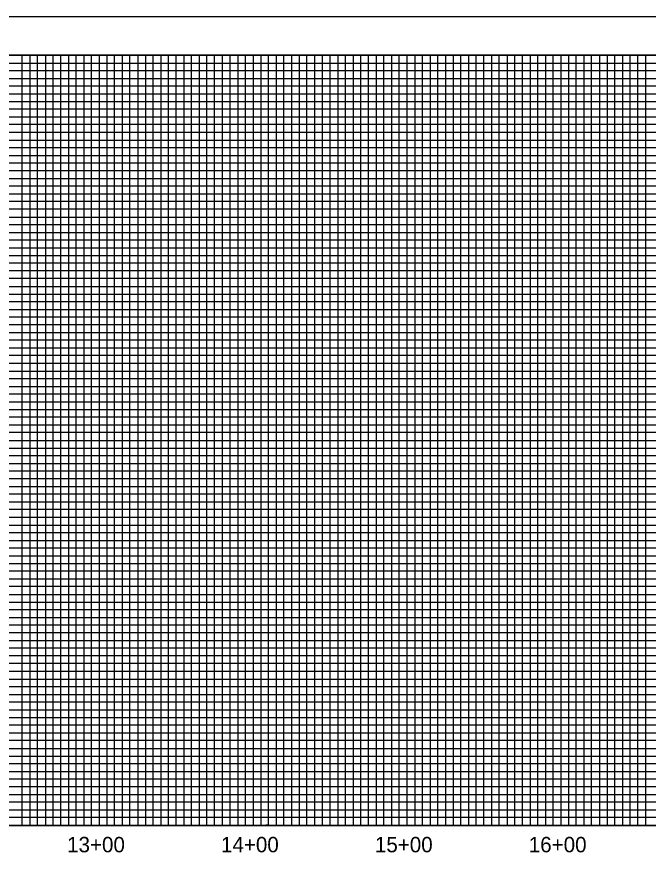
# Model space of a CAD drawing. Extents: x 505602 to 507286, y 483109 to 489436.
# Drawn here: x 506466 to 506876, y 483662 to 484209 of the extents above; entities that cross this region are included whole.
import ezdxf

# ---------------------------------------------------------------- set-up
doc = ezdxf.new("R2010")
doc.units = 0
for name, color, linetype in [('Exist Vertical Profile Vertical Axis Label', 7, 'Continuous'), ('Sheet Layout Profile Border Port 1', 7, 'Continuous'), ('Sheet Plot Border Outside CELL', 7, 'Continuous'), ('Sheet Profile CELL', 7, 'Continuous'), ('Sheet Profile Grid Major CELL', 7, 'Continuous'), ('Sheet Profile Grid Middle CELL', 7, 'Continuous'), ('Sheet Profile Grid Minor CELL', 7, 'Continuous')]:
    doc.layers.add(name, color=color, linetype=linetype)

msp = doc.modelspace()

# ---------------------------------------------------------------- linework, layer by layer
at = {"layer": 'Sheet Layout Profile Border Port 1'}
msp.add_lwpolyline([(506119.08, 484183.71), (507069.08, 484183.71), (507069.08, 483683.71), (506119.08, 483683.71)], close=True, dxfattribs=at)
at = {"layer": 'Sheet Plot Border Outside CELL'}
msp.add_lwpolyline([(505602.08, 483108.71), (507286.08, 483108.71), (507286.08, 484208.71), (505602.08, 484208.71)], close=True, dxfattribs=at)
at = {"layer": 'Sheet Profile CELL'}
msp.add_line((505769.08, 483683.71), (507269.08, 483683.71), dxfattribs=at)
msp.add_lwpolyline([(507269.08, 484183.71), (505769.08, 484183.71), (505769.08, 483133.71), (507269.08, 483133.71)], close=True, dxfattribs=at)
at = {"layer": 'Sheet Profile Grid Major CELL'}
for points in [[(506419.08, 483683.71), (506469.08, 483683.71), (506469.08, 484183.71), (506519.08, 484183.71), (506519.08, 483683.71), (506569.08, 483683.71), (506569.08, 484183.71), (506619.08, 484183.71), (506619.08, 483683.71), (506669.08, 483683.71), (506669.08, 484183.71), (506719.08, 484183.71), (506719.08, 483683.71), (506769.08, 483683.71), (506769.08, 484183.71), (506819.08, 484183.71), (506819.08, 483683.71), (506869.08, 483683.71), (506869.08, 484183.71), (506919.08, 484183.71)], [(505769.08, 484133.71), (507069.08, 484133.71)], [(507069.08, 484083.71), (505769.08, 484083.71), (505769.08, 484033.71), (507069.08, 484033.71)], [(507269.08, 483983.71), (505769.08, 483983.71), (505769.08, 483933.71), (507269.08, 483933.71)], [(507269.08, 483883.71), (505769.08, 483883.71), (505769.08, 483833.71), (507269.08, 483833.71)], [(507269.08, 483783.71), (505769.08, 483783.71), (505769.08, 483783.71), (505769.08, 483733.71), (507269.08, 483733.71)]]:
    msp.add_lwpolyline(points, dxfattribs=at)
at = {"layer": 'Sheet Profile Grid Middle CELL'}
msp.add_line((505769.08, 484158.71), (507069.03, 484158.71), dxfattribs=at)
msp.add_line((505769.08, 484158.71), (507069.03, 484158.71), dxfattribs=at)
for points in [[(506444.08, 483683.71), (506494.08, 483683.71), (506494.08, 484183.71), (506544.08, 484183.71), (506544.08, 483683.71), (506594.08, 483683.71), (506594.08, 484183.71), (506644.08, 484183.71), (506644.08, 483683.71), (506694.08, 483683.71), (506694.08, 484183.71), (506744.08, 484183.71), (506744.08, 483683.71), (506794.08, 483683.71), (506794.08, 484183.71), (506844.08, 484183.71), (506844.08, 483683.71), (506894.08, 483683.71)], [(507069.08, 484108.71), (505769.08, 484108.71), (505769.08, 484058.71), (507069.08, 484058.71)], [(507269.08, 484008.71), (505769.08, 484008.71), (505769.08, 483958.71), (507094.08, 483958.71)], [(507269.08, 483908.71), (505769.08, 483908.71), (505769.08, 483858.71), (507269.08, 483858.71)], [(507269.08, 483808.71), (505769.08, 483808.71), (505769.08, 483758.71), (507269.08, 483758.71)], [(507269.08, 483708.71), (505769.08, 483708.71)]]:
    msp.add_lwpolyline(points, dxfattribs=at)
at = {"layer": 'Sheet Profile Grid Minor CELL'}
for p, q in [((505819.08, 484178.71), (507069.08, 484178.71)), ((507069.08, 484173.71), (505819.08, 484173.36)), ((505819.08, 484168.71), (507069.08, 484168.71)), ((507069.03, 484048.71), (505819.08, 484048.71)), ((507069.08, 484043.71), (505819.08, 484043.71)), ((507069.08, 484038.71), (505819.08, 484038.71)), ((505819.08, 484028.71), (507069.08, 484028.71)), ((507069.08, 484023.71), (505819.08, 484023.71)), ((505819.08, 484018.71), (507219.08, 484018.71)), ((507219.08, 483998.71), (505819.08, 483998.71)), ((505819.08, 483993.71), (507219.08, 483993.71)), ((507219.08, 483973.71), (505819.08, 483973.71)), ((505819.08, 483968.71), (507219.08, 483968.71)), ((507219.08, 483948.71), (505819.08, 483948.71)), ((505819.08, 483943.71), (507219.08, 483943.71)), ((507219.08, 483938.71), (505819.08, 483938.71)), ((505819.08, 483928.71), (507219.08, 483928.71)), ((507219.08, 483923.71), (505819.08, 483923.71)), ((505819.08, 483918.71), (507219.08, 483918.71)), ((507219.08, 483913.71), (505819.08, 483913.71)), ((505819.08, 483903.71), (507219.08, 483903.71)), ((507219.08, 483898.71), (505819.08, 483898.71)), ((505819.08, 483893.71), (507219.08, 483893.71)), ((507219.08, 483888.71), (505819.08, 483888.71)), ((505819.08, 483878.71), (507219.08, 483878.71)), ((507219.08, 483873.71), (505819.08, 483873.71)), ((505819.08, 483868.71), (507219.08, 483868.71)), ((507219.08, 483863.71), (505819.08, 483863.71)), ((505819.08, 483853.71), (507219.08, 483853.71)), ((507219.08, 483848.71), (505819.08, 483848.71)), ((505819.08, 483843.71), (507219.08, 483843.71)), ((507219.08, 483838.71), (505819.08, 483838.71)), ((505819.08, 483828.71), (507219.08, 483828.71)), ((507219.08, 483823.71), (505819.08, 483823.71)), ((505819.08, 483818.71), (507219.08, 483818.71)), ((507219.08, 483813.71), (505819.08, 483813.71)), ((505819.08, 483803.71), (507219.08, 483803.71)), ((507219.08, 483798.71), (505819.08, 483798.71)), ((507219.08, 483793.71), (505819.08, 483793.71)), ((507219.08, 483788.71), (505819.08, 483788.71)), ((505819.08, 483778.71), (507219.08, 483778.71)), ((507219.08, 483773.71), (505819.08, 483773.71)), ((505819.08, 483768.71), (507219.08, 483768.71)), ((507219.08, 483763.71), (505819.08, 483763.71)), ((505819.08, 483753.71), (507219.08, 483753.71)), ((507219.08, 483748.71), (505819.08, 483748.71)), ((505819.08, 483743.71), (507219.08, 483743.71)), ((507219.08, 483738.71), (505819.08, 483738.71)), ((505819.08, 483728.71), (507219.08, 483728.71)), ((507219.08, 483723.71), (505819.08, 483723.71)), ((505819.08, 483718.71), (507219.08, 483718.71)), ((507219.08, 483713.71), (505819.08, 483713.71)), ((505819.08, 483703.71), (507219.08, 483703.71)), ((507219.08, 483698.71), (505819.08, 483698.71)), ((505819.08, 483693.71), (507219.08, 483693.71))]:
    msp.add_line(p, q, dxfattribs=at)
for points in [[(506464.08, 484183.71), (506474.08, 484183.71), (506474.08, 483683.71), (506474.08, 483683.71), (506479.08, 483683.71), (506479.08, 484183.71), (506484.08, 484183.71), (506484.08, 483683.71), (506489.08, 483683.71), (506489.08, 484183.71), (506499.08, 484183.71), (506499.08, 483683.71), (506504.08, 483683.71), (506504.08, 484183.71), (506509.08, 484183.71), (506509.08, 483683.71), (506514.08, 483683.71), (506514.08, 484183.71), (506524.08, 484183.71), (506524.08, 483683.71), (506529.08, 483683.71), (506529.08, 484183.71), (506534.08, 484183.71), (506534.08, 483683.71), (506539.08, 483683.71), (506539.08, 484183.71), (506549.08, 484183.71), (506549.08, 483683.71), (506554.08, 483683.71), (506554.08, 484183.71), (506559.08, 484183.71), (506559.08, 483683.71), (506564.08, 483683.71), (506564.08, 484183.71), (506574.08, 484183.71), (506574.08, 483683.71), (506579.08, 483683.71), (506579.08, 484183.71), (506584.08, 484183.71), (506584.08, 483683.71), (506589.08, 483683.71), (506589.08, 484183.71), (506599.08, 484183.71), (506599.08, 483683.71), (506604.08, 483683.71), (506604.08, 484183.71), (506609.08, 484183.71), (506609.08, 483683.71), (506614.08, 483683.71), (506614.08, 484183.71), (506624.08, 484183.71), (506624.08, 483683.71), (506628.78, 483684.26), (506629.08, 483683.71), (506629.08, 484183.71), (506634.08, 484183.71), (506634.08, 483683.71), (506639.08, 483683.71), (506639.08, 484183.71), (506649.08, 484183.71), (506649.08, 483683.71), (506654.08, 483683.71)], [(506654.08, 483683.71), (506654.08, 484183.71), (506659.08, 484183.71), (506659.08, 483683.71), (506664.08, 483683.71), (506664.08, 484183.71), (506674.08, 484183.71), (506674.08, 483683.71), (506679.08, 483683.71), (506679.08, 484183.71), (506684.08, 484183.71), (506684.08, 483683.71), (506689.08, 483683.71), (506689.08, 484183.71), (506699.08, 484183.71), (506699.08, 483683.71), (506704.08, 483683.71), (506704.08, 484183.71), (506709.08, 484183.71), (506709.08, 483683.71), (506714.08, 483683.71), (506714.08, 484183.71), (506724.08, 484183.71), (506724.08, 483683.71), (506729.08, 483683.71), (506729.08, 484183.71), (506734.08, 484183.71), (506734.08, 483683.71), (506739.08, 483683.71), (506739.08, 484183.71), (506749.08, 484183.71), (506749.08, 483683.71), (506754.08, 483683.71), (506754.08, 484183.71), (506759.08, 484183.71), (506759.08, 483683.71), (506764.08, 483683.71), (506764.08, 484183.71), (506774.08, 484183.71), (506774.08, 483683.71), (506779.08, 483683.71), (506779.08, 484183.71), (506784.08, 484183.71), (506784.08, 483683.71), (506789.08, 483683.71), (506789.08, 484183.71), (506799.08, 484183.71), (506799.08, 483683.71), (506804.08, 483683.71), (506804.08, 484183.71), (506809.08, 484183.71), (506809.08, 483683.71), (506814.08, 483683.71), (506814.08, 484183.71), (506824.08, 484183.71), (506824.08, 483683.71), (506829.08, 483683.71), (506829.08, 484183.71), (506834.08, 484183.71), (506834.08, 483683.71), (506839.08, 483683.71), (506839.08, 484183.71), (506849.08, 484183.71), (506849.08, 483683.71), (506854.08, 483683.71), (506854.08, 484183.71), (506859.08, 484183.71), (506859.08, 483683.71), (506864.08, 483683.71), (506864.08, 484183.71), (506874.08, 484183.71), (506874.08, 483683.71), (506879.08, 483683.71)], [(507069.08, 484163.71), (505819.08, 484163.71), (505819.08, 484153.71), (507069.08, 484153.71)], [(507069.03, 484148.71), (505819.08, 484148.71), (505819.08, 484143.71), (507069.08, 484143.71)], [(507069.08, 484138.71), (505819.08, 484138.71), (505819.08, 484128.71), (507069.08, 484128.71)], [(507069.08, 484123.71), (505819.08, 484123.71), (505819.08, 484118.71), (507069.08, 484118.71)], [(507069.08, 484113.71), (505819.08, 484113.71), (505819.08, 484103.71), (507069.08, 484103.71)], [(507069.08, 484098.71), (505819.08, 484098.71), (505819.08, 484093.71), (507069.08, 484093.71)], [(507069.08, 484088.71), (505819.08, 484088.71), (505819.08, 484078.71), (507069.08, 484078.71)], [(507069.08, 484073.61), (505819.18, 484073.61), (505819.18, 484068.71), (507069.08, 484068.71)], [(507069.08, 484063.71), (505819.08, 484063.71), (505819.08, 484053.71), (507069.08, 484053.71)], [(507219.08, 484013.71), (505819.08, 484013.71), (505819.08, 484003.71), (507219.08, 484003.71)], [(507219.08, 483988.71), (505819.08, 483988.71), (505819.08, 483978.71), (507219.08, 483978.71)], [(507219.08, 483963.71), (505819.08, 483963.71), (505819.08, 483953.71), (507219.08, 483953.71)], [(507219.08, 483688.71), (505819.08, 483688.71)]]:
    msp.add_lwpolyline(points, dxfattribs=at)

# ---------------------------------------------------------------- texts
at = {"layer": 'Exist Vertical Profile Vertical Axis Label'}
for s, p in [('13+00', (506498.21, 483666.21)), ('14+00', (506598.21, 483666.21)), ('15+00', (506698.21, 483666.21)), ('16+00', (506798.21, 483666.21))]:
    msp.add_text(s, height=10, dxfattribs=at).set_placement(p)

doc.saveas('drawing.dxf')
